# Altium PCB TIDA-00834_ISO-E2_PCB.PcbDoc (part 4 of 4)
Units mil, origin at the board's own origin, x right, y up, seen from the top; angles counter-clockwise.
Board outline 9055.12 x 4133.86 mil, 4 copper layers (Top Layer, GND, PWR, Bottom Layer), stack 61.92 mil thick; 647 components, 282 nets, 1430 pads, 409 vias.
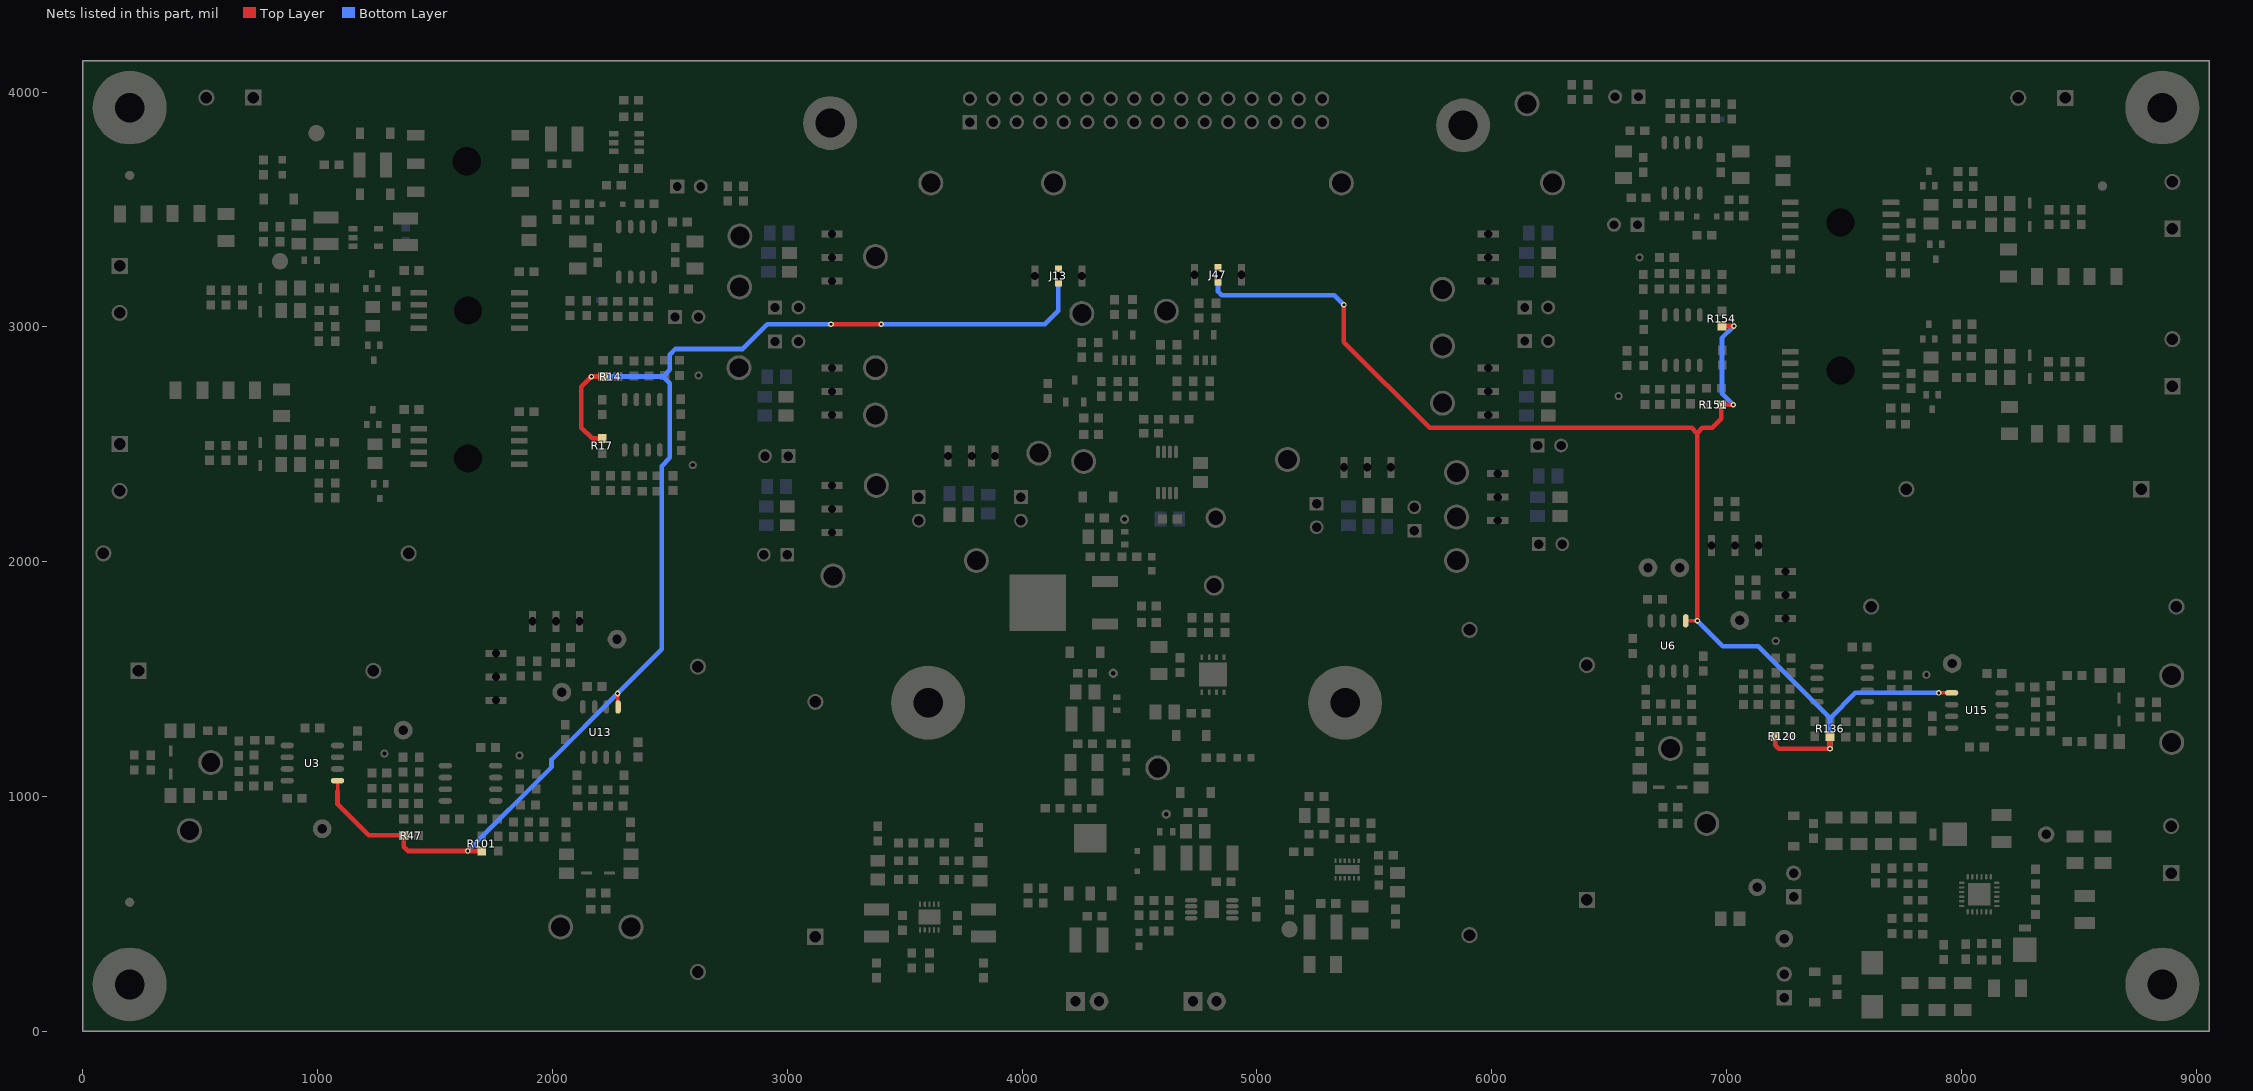
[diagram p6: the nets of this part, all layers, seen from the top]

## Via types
v1: diameter 24, hole 12, Top Layer to Bottom Layer, tented both sides, 388 vias
v2: diameter 19.68, hole 7.87, Top Layer to Bottom Layer, tented top, 15 vias
v3: diameter 19.68, hole 7.87, Top Layer to Bottom Layer, 5 vias
v4: diameter 40, hole 20, Top Layer to Bottom Layer, 1 vias

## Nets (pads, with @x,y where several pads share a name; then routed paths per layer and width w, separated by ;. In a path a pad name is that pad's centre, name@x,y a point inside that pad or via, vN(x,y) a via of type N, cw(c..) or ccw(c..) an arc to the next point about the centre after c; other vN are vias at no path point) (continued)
VBIAS: J13.2 R14.1 R17.1 R47.1 R101.1 U3.5 U13.5 | length 5956.5
  Top Layer w10: R47.1@1365.59,835.27 R47.1@1366.59,834.27 ; U13.5@2277.35,1383.99 U13.5@2279.41,1381.92
  Top Layer w15: 1084.88,1023.19 U3.5@1084.88,1067.52 ; U13.5@2277.35,1383.99 v1(2277.35,1439.09)
  Top Layer w20: 1084.88,1023.19 1084.88,967.72 1217.33,835.27 R47.1@1365.59,835.27 ; R47.1@1366.59,834.27 1366.59,786 1384,768.6 v1(1639.41,768.6) R101.1@1699.41,768.6 ; R17.1@2212.38,2524.84 2169.03,2524.84 2122.38,2571.49 2122.38,2744.86 v1(2165.87,2788.35) R14.1@2215.89,2788.35 ; v1(3186,3011) v1(3400,3011)
  Bottom Layer w20: v1(1639.41,768.6) 1996,1125.19 1996,1157.74 v1(2277.35,1439.09) 2465,1626.74 2465,2407.57 2500,2442.57 2500,2759.77 2471.42,2788.35 ; v1(2165.87,2788.35) 2471.42,2788.35 ; v1(3186,3011) 2915,3011 2810,2906 2524,2906 2500,2882 2500,2816.92 2471.42,2788.35 ; v1(3400,3011) 4097,3011 4154,3068 J13.2@4154,3217
VBIASB: J47.2 R120.1 R136.1 R151.1 R154.1 U6.5 U15.5 | length 5729
  Top Layer w15: U6.5@6825.43,1748.54 v1@6874.8,1748.54 ; v1(7902.91,1441.65) U15.5@7957.83,1441.65
  Top Layer w20: v1(5370,3094) 5370,2935 5735,2570 6851,2570 6873,2548 6874.8,2548 ; v1@6874.8,1748.54 6874.8,2548 ; R154.1@6980,3003.5 v1(7030.8,3003.5) ; v1(7028.25,2668.7) R151.1@6977.45,2668.7 6977.45,2608.45 6939,2570 6896.8,2570 6874.8,2548 ; R120.1@7206.79,1256.2 7206.79,1218.19 7221.12,1203.86 v1(7440.12,1203.86) R136.1@7440.12,1257.36
  Bottom Layer w20: J47.2@4834,3222 4834,3151 4850,3135 5329,3135 v1(5370,3094) ; v1(6875.12,1748.86) 6983.98,1640 7133.98,1640 7440.12,1333.86 ; v1(7028.25,2668.7) 6979.96,2716.99 6979.96,2952.66 v1(7030.8,3003.5) ; v1(7440.12,1203.86) 7440.12,1333.86 ; v1(7902.91,1441.65) 7547.91,1441.65 7440.12,1333.86
pads on no net: D23.3 D24.3 D25.3 D26.3 D27.3 D28.3 D29.3 D30.3 D31.3 D32.3 D33.3 D34.3 D35.3 D36.3 D37.3 D38.3 FID1.1 FID2.1 FID3.1 FID4.1 FID5.1 FID6.1 H1.1 H2.1 H3.1 H4.1 H9.1 H11.1 H13.1 H14.0 H15.1 H16.0 J1.2 J2.2 J31.2 J34.2 J48.2 J49.2 T1.3 T1.4 T2.3 T2.4 T3.3 T3.4 T4.3 T4.4 U5.12 U5.20 U10.1 U10.3 U10.7 U10.8 U11.2 U11.3 U11.6 U12.7 U24.4 U24.5 U26.13@5356.73,689.84 U26.13@5410.59,689.84

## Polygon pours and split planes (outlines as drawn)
NetC155_1 on Top Layer "NETC155_1_L01_P113" (solid, remove dead copper, pour order 113): 5453.5,640 5453.5,651.5 5463,661 5481,661 5502,640 5513.5,640 5543.5,640 5563.5,620 5613.5,620 5623.5,620 5628.5,615 5628.5,512.5 5621,505 5552,505 5538,519 5538,550.5 5488.5,600 5470.5,618 5453.5,635
GND1 on Top Layer "GND1_L01_P133" (solid, remove dead copper, pour order 133): 5560,790 5560,730 5570,720 5570,680 5570,655 5575,650 5630,650 5660,650 5680,670 5680,790 5660,810 5580,810
NetC161_1 on Top Layer "NETC161_1_L01_P131" (solid, remove dead copper, pour order 131): 3715,817.09 3725,827.09 3875,827.09 3885,817.09 3885,722.09 3885,707.09 3875,697.09 3820,697.09 3775,697.09 3765,687.09 3765,632.09 3765,602.09 3745,582.09 3705,582.09 3690,567.09 3680,567.09 3670,577.09 3715,622.09
NetC161_2 on Top Layer "NETC161_2_L01_P129" (solid, remove dead copper, pour order 129): 3650,812.09 3655,817.09 3665,817.09 3685,817.09 3690,812.09 3690,732.09 3690,627.09 3650,587.09 3640,587.09 3632,595.09 3632,749.09 3650,767.09 3650,802.09 3650,812.09 3655,817.09
NetC159_2 on Top Layer "NETC159_2_L01_P127" (solid, remove dead copper, pour order 127): 3515,812.09 3515,817.09 3520,822.09 3550,822.09 3555,817.09 3555,787.09 3555,783.09 3575,763.09 3575,572.55 cw(c3569.59,581.74) 3570,571.09 3565,572.09 3515,622.09
NetC159_1 on Top Layer "NETC159_1_L01_P125" (solid, remove dead copper, pour order 125): 3325,822.09 3330,827.09 3370,827.09 3405,827.09 3415,817.09 3415,792.09 3415,757.09 3425,747.09 3470,747.09 3480,747.09 3490,737.09 3490,712.09 3490,617.09 3535,572.09 3535,567.09 3525,557.09 3500,557.09 3440,617.09 3440,692.09 3430,702.09 3400,702.09 3330,702.09 3325,707.09
NetC164_2 on Top Layer "NETC164_2_L01_P123" (solid, remove dead copper, pour order 123): 3670,437.09 3680,447.09 3725,447.09 3760,447.09 3780,427.09 3895,427.09 3900,427.09 3910,417.09 3910,285 3900,275 3760,275 3750,285 3750,337.09 3670,417.09
GND1 on Top Layer "GND1_L01_P121" (solid, remove dead copper, pour order 121): 3325,662.09 3335,672.09 3380,672.09 3405,672.09 3415,662.09 3415,613.09 3415,607.09 3455,567.09 3510,512.09 3590,512.09 3670,512.09 3715,557.09 3760,557.09 3780,577.09 3790,587.09 3790,647.09 3790,652.09 3800,662.09 3875,662.09 3900,662.09 3915,647.09 3920,642.09 3920,572.09 3920,517.09 3905,502.09 3900,497.09 3825,497.09 3765,497.09 3745,477.09 3710,477.09 3680,477.09 3658.62,455.7 3628.77,455.7 3560.3,455.7 3543.91,472.09 3490,472.09 3455,472.09 3430,497.09 3340,497.09 3335,497.09 3325,507.09
GND1 on Top Layer "GND1_L01_P115" (solid, remove dead copper, pour order 115): 5198.5,780 5198.5,790 5198.5,795 5203.5,800 5238.5,800 5240.69,800 5243.5,797.18 5243.5,720 5253.5,710 5258.5,705 5348.5,705 5428.5,705 5433.5,700 5433.5,685 5433.5,680 5428.5,675 5258.5,675 5248.5,665 5248.5,645 5248.5,625 5273.5,600 5288.5,585 5288.5,525 5248.5,485 5248.5,388.5 5240,380 5208.28,380 5198.5,389.77 5198.5,795
NetC153_1 on Top Layer "NETC153_1_L01_P111" (solid, remove dead copper, pour order 111): 5265,1025 5265,788.5 5298.51,755 5338.5,755 5345,761.5 5345,775 5340,780 5323.51,780 5303.5,800 5303.5,835 5303.5,1026.5 5295,1035 5275,1035
NetC151_2 on Top Layer "NETC151_2_L01_P109" (solid, remove dead copper, pour order 109): 5369.5,660 5369.5,621 5369.5,607 5349.5,587 5336.5,587 5327.5,587 5315.5,575 5315.5,399 5321.5,393 5344.5,393 5356.5,393 5363.5,400 5363.49,569.98 5378.5,585 5378.5,590 5378.5,660
+6V_VDC on Top Layer "+6V_VDC_L01_P072" (solid, remove dead copper, pour order 72): 1205,3850 1205,3535 1188.98,3518.98 1091.02,3518.98 1075,3535 1075,3610 1075,3725 1075,3810 1075,3850 1085,3860 1175,3860 1195,3860
AGND on Top Layer "Top Layer-No Net" (solid, remove dead copper, pour order 58): 4542.4,1545 4717.4,1545 4742.4,1570 4892.05,1570 4902.4,1559.65 4902.4,1480.35 4892.05,1470 4712.4,1470 4682.4,1440 4607.4,1440 4592.4,1425 4592.4,1305 4577.4,1290 4542.4,1290 4527.4,1305 4527.4,1530
+3.3V on Top Layer "Top Layer-No Net" (solid, remove dead copper, pour order 56): 4446.5,2301 4446.5,2245.15 4386.5,2185.15 4386.5,2076 4381.5,2071 4336.5,2071 4331.5,2076 4331.5,2231 4371.5,2271 4371.5,2301 4381.5,2311 4436.5,2311
AGND on Top Layer "Top Layer-No Net" (solid, remove dead copper, pour order 54): 4271.5,2301 4271.5,2236 4281.5,2226 4306.5,2226 4311.5,2221 4311.5,2008.5 4186.5,1883.5 4186.5,1721.5 4170,1705 3964,1705 3948,1721 3948,1928.56 3964.44,1945 4059,1945 4186.5,2072.5 4186.5,2301 4196.5,2311 4261.5,2311
+12V on Top Layer "Top Layer-No Net" (solid, remove dead copper, pour order 50): 4330,1640 4420,1640 4435,1625 4435,1500 4415,1480 4370,1480 4362.91,1472.91 4362.91,1460 4362.91,1420 4352.91,1410 4322.91,1410 4292.91,1410 4282.91,1420 4282.91,1550 4282.91,1555 4312.91,1585 4312.91,1622.91
NetC54_2 on Top Layer "Top Layer-No Net" (solid, remove dead copper, pour order 48): 4235,1175 4235,995 4250,980 4250,935 4245,930 4145,930 4140,935 4140,1175 4145,1180 4230,1180
NetC54_1 on Top Layer "Top Layer-No Net" (solid, remove dead copper, pour order 46): 4365,760 4220,760 4215,765 4215,880 4225,890 4265,890 4277.91,902.91 4277.91,1265 4297.91,1285 4297.91,1360 4297.91,1373.15 4307.91,1383.15 4334.84,1383.15 4364.76,1383.15 4372.91,1375 4372.91,1355 4372.91,1280 4392.91,1260 4397.91,1255 4397.91,1200 4372.91,1175 4372.91,767.91
AGND on Top Layer "Top Layer-No Net" (solid, remove dead copper, pour order 44): 4095,1640 4210,1640 4222.91,1627.09 4222.91,1565 4227.91,1560 4251.46,1560 4257.91,1553.54 4257.91,1403.15 4237.91,1383.15 4237.91,1270 4257.91,1250 4257.91,1215 4247.91,1205 4095,1205 4085,1215 4085,1630
AGND on Top Layer "Top Layer-No Net" (solid, remove dead copper, pour order 42): 4015,565 4115,565 4125,555 4125,520 4130,515 4162.92,515 4257.91,515 4287.91,515 4292.91,510 4292.91,485 4292.91,465 4282.91,455 4252.91,425 4252.91,400 4252.91,335 4242.91,325 4187.91,325 4015,325 4005,335 4005,555
+14V on Top Layer "Top Layer-No Net" (solid, remove dead copper, pour order 40): 4317.91,512.91 4325,520 4415,520 4420,515 4420,305 4410,295 4330,295 4317.91,307.09
-14V on Top Layer "Top Layer-No Net" (solid, remove dead copper, pour order 38): 4867.4,795 4877.4,805 4962.4,805 4972.4,795 4972.4,620 4957.4,605 4882.4,605 4867.4,620
-12V on Top Layer "Top Layer-No Net" (solid, remove dead copper, pour order 36): 4669.4,940.6 4625,985 4625,1065 4635,1075 4685,1075 4692.4,1067.6 4692.4,992.6 4722.4,962.6 4722.4,920 4722.4,830 4712.4,820 4678.4,820 4669.4,829
AGND on Top Layer "Top Layer-No Net" (solid, remove dead copper, pour order 34): 4604.69,441.64 4609.69,446.64 4769.65,446.64 4777.4,454.4 4777.4,590 4765.76,601.64 4684.69,601.64 4674.69,611.64 4674.69,780.9 4685.42,791.64 4744.69,791.64 4749.69,796.64 4749.69,961.64 4784.69,996.64 4784.69,1091.64 4794.69,1101.64 4855.76,1101.64 4867.4,1090 4867.4,855 4809.69,797.28 4809.69,686.64 4837.4,658.92 4837.4,394.36 4824.69,381.64 4615.76,381.64 4604.68,392.72
NetC35_1 on Top Layer "Top Layer-No Net" (solid, remove dead copper, pour order 20): 7210.12,798.86 7220.12,808.86 7325.12,808.86 7335.12,818.86 7335.12,833.86 7345.12,843.86 7405.12,843.86 7425.12,823.86 7815.12,823.86 7835.12,843.86 7835.12,973.86 7840.12,978.86 7890.12,978.86 7895.12,973.86 7895.12,763.86 7945.12,713.86 7945.12,623.86 7945.12,603.86 7935.12,593.86 7900.12,593.86 7880.12,613.86 7880.12,723.86 7850.12,753.86 7665.12,753.86 7655.12,743.86 7655.12,688.86 7645.12,678.86 7570.12,678.86 7560.12,688.86 7560.12,743.86 7550.12,753.86 7370.12,753.86 7350.12,733.86 7350.12,648.86 7340.12,638.86 7220.12,638.86 7210.12,648.86
GND1 on Top Layer "Top Layer-No Net" (solid, remove dead copper, pour order 28): 8380.12,893.86 8125.12,893.86 8105.12,913.86 8105.12,963.86 8120.12,978.86 8955.12,978.86 8985.12,948.86 8985.12,828.86 8965.12,808.86 8465.12,808.86 8460.12,808.86 8445.12,823.86 8445.12,873.86 8425.12,893.86
+5V_IN on Top Layer "Top Layer-No Net" (solid, remove dead copper, pour order 6): 8140.12,608.86 8140.12,683.86 8175.12,718.86 8360.12,718.86 8385.12,743.86 8970.12,743.86 8985.12,728.86 8985.12,568.86 8965.12,548.86 8380.12,548.86 8365.12,563.86 8365.12,663.86 8355.12,673.86 8200.12,673.86 8190.12,663.86 8190.12,608.86
NetD4_1 on Top Layer "Top Layer-No Net" (solid, remove dead copper, pour order 24): 8215.12,398.86 8200.12,383.86 8200.12,263.86 8225.12,238.86 8225.12,113.86 8235.12,103.86 8330.12,103.86 8340.12,113.86 8340.12,388.86 8330.12,398.86
NetD7_1 on Top Layer "Top Layer-No Net" (solid, remove dead copper, pour order 18): 7920.12,973.86 7920.12,773.86 7965.12,728.86 7965.12,623.86 7980.12,608.86 8010.12,608.86 8015.12,613.86 8015.12,643.86 8005.12,653.86 8005.12,723.86 8050.12,768.86 8250.12,768.86 8270.12,788.86 8270.12,813.86 8250.12,833.86 8070.12,833.86 8055.12,848.86 8055.12,973.86 8050.12,978.86 7925.12,978.86
GND1 on Top Layer "Top Layer-No Net" (solid, remove dead copper, pour order 16): 7210.12,923.86 7210.12,907.86 7219.12,898.86 7312.12,898.86 7315.12,898.86 7345.12,868.86 7389.12,868.86 7400.12,868.86 7415.12,883.86 7418.12,886.86 7692.12,886.86 7803.12,886.86 7810.12,893.86 7810.12,973.86 7805.12,978.86 7223.12,978.86 7210.12,965.86 7210.12,924.86
NetD4_2 on Top Layer "Top Layer-No Net" (solid, remove dead copper, pour order 26): 8115.12,509.86 8115.12,448.86 8130.12,433.86 8200.12,433.86 8205.12,433.86 8210.12,428.86 8215.12,423.86 8245.12,423.86 8345.12,423.86 8370.12,398.86 8370.12,343.86 8380.12,333.86 8610.12,333.86 8620.12,343.86 8620.12,463.86 8620.12,473.86 8610.12,483.86 8605.12,488.86 8485.12,488.86 8395.12,488.86 8365.12,458.86 8260.12,458.86 8255.12,458.86 8230.12,483.86 8230.12,518.86 8230.12,523.86 8220.12,533.86 8215.12,538.86 8165.12,538.86 8144.12,538.86
NetC25_1 on Top Layer "Top Layer-No Net" (solid, remove dead copper, pour order 32): 7160.12,293.86 7160.12,238.86 7190.12,208.86 7255.12,208.86 7290.12,208.86 7320.12,238.86 7380.12,238.86 7420.12,238.86 7430.12,228.86 7430.12,223.86 7430.12,208.86 7435.12,203.86 7440.12,198.86 7465.12,198.86 7500.12,198.86 7510.12,208.86 7510.12,233.86 7520.12,243.86 7675.12,243.86 7695.12,243.86 7710.12,228.86 7710.12,213.86 7710.12,188.86 7720.12,178.86 7770.12,178.86 8070.12,178.86 8080.12,168.86 8080.12,143.86 8087.76,136.22 8157.48,136.22 8165.12,143.86 8165.12,238.86 8155.12,248.86 8115.12,248.86 8105.12,258.86 8105.12,318.86 8100.12,323.86 8005.12,323.86 8000.12,318.86 8000.12,258.86 7990.12,248.86 7800.12,248.86 7785.12,263.86 7785.12,303.86 7785.12,333.86 7770.12,348.86 7768.98,350 7691.97,350 7191.26,350 7160.12,318.86
GND1 on Top Layer "GND1_L01_P068" (solid, remove dead copper, pour order 68): 7325.12,133.86 7335.12,143.86 7400.12,143.86 7420.12,143.86 7430.12,153.86 7430.12,163.86 7440.12,173.86 7510.12,173.86 7550.12,173.86 7570.12,153.86 7640.12,153.86 7690.12,153.86 7705.12,138.86 7730.12,113.86 7755.12,113.86 8155.12,113.86 8165.12,103.86 8165.12,73.86 8165.12,53.86 8140.12,28.86 8005.12,28.86 7350.12,28.86 7325.12,53.86
+5.0V_VDC on Top Layer "+5.0V_VDC_L01_P077" (solid, remove dead copper, pour order 77): 700,3670 750,3670 790,3670 795,3665 795,3630 795,3410 790,3405 725,3405 700,3405 690,3415 690,3660
NetC49_1 on Top Layer "NETC49_1_L01_P135" (solid, remove dead copper, pour order 135): 4425,2084 4441,2084 4456.16,2084 4460,2080.16 4460,2050 4445,2035 4445,2021 4445,1905 4430,1890 4405,1890 4300,1890 4295,1895 4295,1904 4295,1950 4334,1989 4335,1990 4335,2008 4335,2036 4339,2040 4361,2040 4381,2040
NetC157_2 on Top Layer "NETC157_2_L01_P137" (solid, remove dead copper, pour order 137): 3530,450 3465,450 3455,450 3435,430 3330,430 3305,430 3295,420 3295,390 3295,310 3295,295 3295,285 3305,275 3370,275 3435,275 3445,285 3450,290 3450,360 3450,365 3460,375 3480,395 3510,395 3520,395 3538.07,413.07 3538.07,441.81
GND1 on GND "GND1_L02_P060" (solid, remove dead copper, pour order 60): 8975,1000 7100,1000 7025,925 7025,300 6975,250 5760,250 5725,285 5725,980 5705,1000 5010,1000 5000,990 5000,280 4970,250 4505,250 4455,300 3880,300 3850,330 3850,860 3835,875 3335,875 3325,865 3325,250 3325,50 3345,30 5015,30 8605,30 8625,50 8625,410 8639.99,424.99 8974.99,424.99 9000,450 9000,975
GND2 on GND "GND2_L02_P064" (solid, remove dead copper, pour order 64): 7290,4035 6250,4035 6238.39,4023.39 6238.39,3918.34 6388.39,3768.34 6388.39,3578.34 6390.35,3464.65 6480,3375 7075,3375 7125,3425 7125,3610 7195,3680 7285,3680 7300,3695 7300,3775 7300,4025
GND_VDC on GND "GND_VDC_L02_P075" (solid, remove dead copper, pour order 75): 50,3700 75,3725 200,3725 400,3725 425,3750 425,4075 450,4100 1350,4100 1450,4100 1475,4075 1475,4000 1475,2275 1475,2250 1450,2225 1275,2225 75,2225 50,2250 50,3700
GND_VDC on GND "GND_VDC_L02_P081" (solid, remove dead copper, pour order 81): 7650,4050 7650,4075 7675,4100 7800,4100 8600,4100 8625,4075 8625,3750 8650,3725 8675,3725 9000,3725 9025,3700 9025,2520 9000,2495 7680,2495 7650,2525
GND on GND "GND_L02_P087" (solid, remove dead copper, pour order 87): 1825,4000 1850,4025 2175,4025 2800,4025 2825,4025 2850,4000 2850,3850 2850,3025 2800,2975 2250,2975 2075,2975 2000,3050 2000,3275 2000,3400 1975,3425 1925,3425 1850,3425 1825,3450
AGND on GND "AGND_L02_P073" (solid, remove dead copper, pour order 73): 50,1450 50,1925 50,1950 75,1975 1800,1975 1825,2000 1825,3375 1845,3395 1955,3395 1975,3375 1975,2954 2004,2925 2790,2925 2875,3010 2875,3850 2875,4006 2894,4025 6075,4025 6350,3750 6350,3460 6460,3350 6550,3350 7100,3350 7150,3400 7150,3600 7200,3650 7285,3650 7300,3635 7300,2250 7325,2225 8975,2225 9025,2175 9025,1050 9000,1025 7075,1025 7000,950 7000,750 7000,325 6950,275 5770,275 5750,295 5750,995 5720,1025 5000,1025 4975,1000 4975,295 4955,275 4520,275 4445,350 4185,350 4160,325 3890,325 3875,340 3875,895 3860,910 3320,910 3300,890 3300,275 3300,50 450,50 425,75 425,150 425,400 400,425 250,425 75,425 50,450 49.41,450.59
+5.0V_VDC on PWR "+5.0V_VDC_L03_P079" (solid, remove dead copper, pour order 79): 100,3650 125,3675 230,3675 450,3675 475,3700 475,3890 475,4000 500,4025 570,4025 865,4025 1400,4025 1425,4000 1425,3325 1450,3300 1450,3275 1425,3250 1425,2725 1450,2700 1450.75,2699.25 1450.75,2674.25 1450.75,2665.75 1425,2640 1425,2590 1425,2300 1400,2275 1275,2275 125,2275 100,2300
+5.0V_VDC on PWR "+5.0V_VDC_L03_P085" (solid, remove dead copper, pour order 85): 7700,4025 7725,4050 7800,4050 8550,4050 8575,4025 8575,3725 8575,3700 8600,3675 8675,3675 8925,3675 8950,3650 8950,3550 8950,2550 8925,2525 7750,2525 7725,2525 7700,2525 7675,2550 7675,2575 7700,2600 7700,3150 7675,3175 7675,3200 7700,3225 7700,3275
+12V on PWR "+12V_L03_P099" (solid, remove dead copper, pour order 99): 100,1900 125,1925 1825,1925 1875,1975 1875,3950 1900,3975 7225,3975 7250,3950 7250,2225 7300,2175 8925,2175 8950,2150 8950,1100 8925,1075 7025,1075 6950,1000 6950,350 6925,325 4025,325 4000,300 4000,125 3975,100 500,100 475,125 475,425 425,475 125,475 100,500
-12V on Bottom Layer "-12V_L04_P097" (solid, remove dead copper, pour order 97): 800,75 825,50 3525,50 3910,50 4050,190 4050,645 4080,675 4150,675 4835,675 4955,675 4980,650 4980,300 5100,180 6760,180 7175,595 7175,975 7250,1050 7430,1050 7750,1370 8125,1370 8210,1455 8210,1565 8195,1580 8160,1580 8150,1570 8150,1480 8085,1415 7690,1415 7575,1300 7450,1175 7425,1175 7410,1190 7410,1315 7120,1605 6995,1605 6975,1585 6945,1555 6885,1555 6880,1550 6880,1520 6885,1515 6985,1515 7015,1545 7055,1545 7075,1525 7270,1330 7270,1195 7250,1175 7125,1175 7015,1065 7015,725 6630,340 5195,340 5125,410 5125,1170 5085,1210 3930,1210 3890,1170 3890,305 3785,200 3465,200 1015,200 975,240 975,555 1020,600 2114,600 2450,936 2450,1150 2450,1175 2435,1190 2350,1190 2345,1185 2345,1145 2390,1100 2390,1045 2365,1020 2180,1020 2085,925 1850,690 1605,690 1575,720 1575,895 1655,975 1655,1633.22 1836.78,1815 2265,1815 2425,1975 2425,2450 2425,2575 2275,2725 2150,2725 2125,2700 2122.38,2697.38 2122.38,2625 2122.38,2614.84 2212.38,2524.84 2379.5,2357.72 2379.5,2327.2 2379.5,2004.5 2275,1900 1900,1900 1825,1900 1570,1645 1570,975 1395,800 915,800 890,825 890,1005 885,1010 840,1010 800,970

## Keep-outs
Keep-Out Layer:
  lines w10: 25,400 400,400 400,0 ; 25,3743.7 400,3743.7 400,4108.86 ; 8650,25 8650,400 9025,400 ; 8655.12,4108.86 8655.12,3743.7 9030.12,3743.7 ; 25,25 9030.12,25 9030.12,4108.86 25,4108.86 25,25
  text ".Layer_Name" at 577,-858.49 h60

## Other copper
Top Layer:
  region net +5V_IN: 8040.12,703.86 8040.12,648.86 8045.12,643.86 8105.12,643.86 8110.12,648.86 8110.12,703.86 8105.12,708.86 8045.12,708.86
  text ".Layer_Name" at 577,-858.49 h60
GND:
  pour cut-out: 5730,3990 5730,3715 6030,3715 6030,3990
  pour cut-out: 3032.4,4005.35 3032.4,3730.35 3332.4,3730.35 3332.4,4005.35
  pour cut-out: 3400,1600 3400,1200 3800,1200 3800,1600
  pour cut-out: 5175,1600 5175,1200 5575,1200 5575,1600
  text ".Layer_Name" at 577,-858.49 h60
PWR:
  pour cut-out: 4050,325 4050,485 4085,485 4085,325
  pour cut-out: 5730,3990 5730,3715 6030,3715 6030,3990
  pour cut-out: 3032.4,4005.35 3032.4,3730.35 3332.4,3730.35 3332.4,4005.35
  pour cut-out: 3400,1600 3400,1200 3800,1200 3800,1600
  pour cut-out: 5175,1600 5175,1200 5575,1200 5575,1600
  pour cut-out: 3715,3975 3715,3825 3725,3815 5315,3815 5330,3830 5330,3960 5345,3975 5345,3830 5325,3810 3720,3810 3710,3820 3710,3970
  text ".Layer_Name" at 577,-858.49 h60
Bottom Layer:
  text ".Layer_Name" at 577,-858.49 h60
Multi-Layer:
  pour cut-out: 1495.39,4011 1495.39,2200 0,2200 0,2080 1795,2080 1795,2099.61 1795.39,2100 1795.39,4011
  pour cut-out: 7633,4011 7633,2512 7670,2475 9055.12,2475 9055.12,2360 7380,2360 7333,2407 7333,4011

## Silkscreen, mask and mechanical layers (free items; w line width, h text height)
Top Overlay:
  drawing of 256 lines, arcs and shapes, not listed
  text "2" at 3760,4035 h60
  text "14" at 4335,4035 h60
  text "20" at 4635,4035 h60
  text "8" at 4055,4030 h60
  text "26" at 4930,4030 h60
  text "32" at 5225,4030 h60
  text "19" at 4627.4,3740 h60
  text "7" at 4070,3735 h60
  text "13" at 4345,3735 h60
  text "25" at 4935,3735 h60
  text "31" at 5230,3735 h60
  text "1" at 3765,3730 h60
  text "TIDA-00834_ISO-E2" at 1669,100 h108.27
  text ".Layer_Name" at 577,-858.49 h60
Bottom Overlay:
  text "2" at 3780,4035 h60
  text "14" at 4425,4035 h60
  text "20" at 4735,4035 h60
  text "8" at 4115,4030 h60
  text "26" at 5030,4030 h60
  text "32" at 5325,4030 h60
  text "19" at 4720,3745 h60
  text "7" at 4090,3735 h60
  text "13" at 4445,3735 h60
  text "25" at 5030,3735 h60
  text "31" at 5310,3735 h60
  text "1" at 3785,3730 h60
  text ".Layer_Name" at 577,-858.49 h60
Top Paste:
  text ".Layer_Name" at 577,-858.49 h60
Bottom Paste:
  text ".Layer_Name" at 577,-858.49 h60
Top Solder:
  text ".Layer_Name" at 577,-858.49 h60
  text ".Layer_Name" at 577,-858.49 h60
Bottom Solder:
  text ".Layer_Name" at 577,-858.49 h60
Drill Guide:
  text ".Layer_Name" at 577,-858.49 h60
M1 Board Outline:
  the board outline again, w10
  text ".Layer_Name" at 584,-851.99 h60
M2 Board Dimensions:
  rectangle: 125,-400 500,-275
  rectangle: 0,-275 125,-150
  lines w7: 0,-275 1000,-275 ; 125,-400 125,-150 ; 250,-400 250,-150 ; 500,-400 500,-150 ; 750,-400 750,-150 ; 0,-400 0,-150 1000,-150 1000,-400 0,-400
M3 3D STEP Top:
  text ".Layer_Name" at 577,-858.49 h60
M4 3D STEP Bottom:
  text ".Layer_Name" at 577,-858.49 h60
M5 Assembly Top:
  circle w6: c4762.4,1445 r7.07
  circle w6: c1132,3417 r5
  circle w6: c1205,3136 r5
  circle w6: c1266,2950 r5
  circle w6: c1209,2552 r5
  circle w6: c1289,2362 r5
  circle w6: c2242,3822 r5
  circle w6: c4397.6,2839 r5
  circle w6: c4742.6,2840 r5
  circle w6: c4230,631 r5
  circle w6: c7901,2740 r5
  circle w6: c7834,2921 r5
  circle w6: c7916,3379 r5
  circle w6: c7834,3573 r5
  circle w6: c4186.6,2658 r5
  lines w4: 4742.4,1425 4742.4,1615 4752.4,1615 4882.4,1615 4882.4,1425 4742.4,1425
  lines w6: 420,1120 425,1115 465,1115 470,1110 ; 420,1170 425,1175 465,1175 470,1180 ; 445,1095 445,1115 ; 445,1135 445,1155 ; 445,1195 445,1175 ; 2145,735 2165,735 ; 2160,760 2165,755 2165,715 2170,710 ; 2185,735 2205,735 ; 2220,710 2225,715 2225,755 2230,760 ; 2245,735 2225,735 ; 6710,1105 6730,1105 ; 6725,1130 6730,1125 6730,1085 6735,1080 ; 6750,1105 6770,1105 ; 6785,1080 6790,1085 6790,1125 6795,1130 ; 6810,1105 6790,1105 ; 8580,1335 8585,1340 8625,1340 8630,1345 ; 8580,1405 8585,1400 8625,1400 8630,1395 ; 8605,1320 8605,1340 ; 8605,1360 8605,1380 ; 8605,1420 8605,1400 ; 445,1115 425,1135 465,1135 445,1115 ; 445,1175 465,1155 425,1155 445,1175 ; 2165,735 2185,715 2185,755 2165,735 ; 2225,735 2205,755 2205,715 2225,735 ; 6730,1105 6750,1125 6750,1085 6730,1105 ; 6790,1105 6770,1085 6770,1125 6790,1105 ; 8605,1340 8585,1360 8625,1360 8605,1340 ; 8605,1400 8625,1380 8585,1380 8605,1400
  lines w10: -292,-930.17 6308,-930.17 ; -292,-726.83 6310,-726.83 ; -292,-523.5 -292,-1133.5 3713,-1133.5 6310,-1133.5 6310,-523.5 -291.5,-523.5 -291.5,-1133.5 1284,-1133.5 ; 2173,-1133.5 2173,-523.5 ; 3440,-726.83 3440,-523.5 ; 4280,-726.83 4280,-523.5 ; 4902,-1140 4902,-937.17
  text "COMPONENTS MARKED 'DNP' SHOULD NOT BE POPULATED." at 1153.5,-318.5 h60
  text "ASSEMBLY VARIANT:" at 1153,-434 h60
  text ".VariantName" at 2189,-434 h60
  text ".PRJ_Number" at 2725,-650 h50
  text "PCB VIEWED FROM TOP SIDE" at -228.5,-655.67 h60
  text "BOARD #:" at 2248,-655.67 h60
  text "REV:" at 3638,-655.67 h60
  text ".PCB_Rev" at 3929.5,-655.67 h60
  text "SVN REV:" at 4476,-655.67 h60
  text ".VersionControl_RevNumber" at 4982,-655.67 h60
  text ".Layer_Name" at 577,-858.49 h60
  text "TID #:" at 2248,-859 h60
  text ".TID" at 2793.5,-859 h60
  text "PLOT NAME =" at -228.5,-1064.34 h60
  text ".plot_File_Name" at 577,-1064.34 h60
  text "GENERATED    :" at 2250,-1064.34 h60
  text ".Print_Date" at 3119.5,-1064.34 h60
  text ".Print_Time" at 3848.5,-1064.34 h60
  text "TEXAS INSTRUMENTS" at 5113,-1064.34 h60
M6 Assembly Bottom:
  circle w6: c7885,3572 r4.12
  circle w6: c7863.88,3377 r4.12
  circle w6: c7884.88,2921 r4.12
  circle w6: c7848.88,2739 r4.12
  circle w6: c1254.88,3137 r4.12
  circle w6: c1214.88,2949 r4.12
  circle w6: c1259.88,2559 r4.12
  circle w6: c1238.88,2359 r4.12
  circle w20: c3683,3870 r14.87
  lines w10: -292.5,-727.33 6309.5,-727.33 ; -290.5,-930.67 6309.5,-930.67 ; 1115.5,-1140.5 1115.5,-937.67 ; 1737.5,-727.33 1737.5,-524 ; 2577.5,-727.33 2577.5,-524 ; 3844.5,-1134 3844.5,-524 ; 4733.5,-1134 6309,-1134 6309,-524 -292.5,-524 -292.5,-1134 2304.5,-1134 6309.5,-1134 6309.5,-524
  text "COMPONENTS MARKED 'DNP' SHOULD NOT BE POPULATED." at 6102,-318 h60
  text ".VariantName" at 5058,-434 h60
  text "ASSEMBLY VARIANT:" at 6097,-434 h60
  text ".PRJ_Number" at 3305,-655 h50
  text ".VersionControl_RevNumber" at 1035.5,-656.17 h60
  text "SVN REV:" at 1541.5,-656.17 h60
  text ".PCB_Rev" at 2088,-656.17 h60
  text "REV:" at 2379.5,-656.17 h60
  text "BOARD #:" at 3769.5,-656.17 h60
  text "PCB VIEWED FROM BOTTOM SIDE" at 6246,-656.17 h60
  text ".Layer_Name" at 5805,-840 h60
  text ".TID" at 3224,-859.5 h60
  text "TID #:" at 3769.5,-859.5 h60
  text "TEXAS INSTRUMENTS" at 904.5,-1064.84 h60
  text ".Print_Time" at 2169,-1064.84 h60
  text ".Print_Date" at 2898,-1064.84 h60
  text "GENERATED    :" at 3767.5,-1064.84 h60
  text ".plot_File_Name" at 5440.5,-1064.84 h60
  text "PLOT NAME =" at 6246,-1064.84 h60
M9 Title Sheet:
  drawing of 57 lines, arcs and shapes, not listed
  text "1" at 739.84,8036.5 h70
  text "2" at 3235.5,8036.5 h70
  text "3" at 5724.84,8036.5 h70
  text "4" at 8231.51,8036.5 h70
  text "5" at 10730.5,8036.5 h70
  text "6" at 13235.5,8036.5 h70
  text "A" at -416.5,6893.5 h70
  text "A" at 14383.5,6893.5 h70
  text "B" at -416.5,4513.5 h70
  text "B" at 14383.5,4513.5 h70
  text "C" at -416.5,2138.5 h70
  text "C" at 14383.5,2138.5 h70
  text "PROJECT TITLE:" at 11343.5,277.5 h45
  text ".PRJ_Title" at 11393.5,144.17 h70
  text "DESIGNED FOR:" at 11343.5,-23.5 h45
  text ".PRJ_Customer" at 11393.5,-163.5 h70
  text "D" at -416.5,-231.5 h70
  text "D" at 14383.5,-231.5 h70
  text "FILE NAME:" at 11343.5,-323.5 h45
  text ".PCB_File_Name_No_Path" at 11393.5,-443.5 h70
  text "Texas Instruments (TI) and/or its licensors do not warrant the accuracy or completeness of this specification" at 6374,-605.34 h45
  text "ENGINEER:" at 11343.5,-613.5 h45
  text "LAYOUT BY:" at 12848.5,-613.5 h45
  text "or any information contained therein. TI and/or its licensors do not warrant that this design will meet" at 6329.01,-718 h45
  text ".PRJ_Engineer" at 11393.5,-768.49 h70
  text ".PCB_Layout" at 12899,-768.49 h70
  text "the specifications, will be suitable for your application or fit for any particular purpose, or will operate in" at 6329.01,-830.67 h45
  text "ALTIUM DESIGNER VERSION:" at 12848.5,-923.5 h45
  text "an implementation. TI and/or its licensors do not warrant that the design is production worthy. You should" at 6329.01,-943.33 h45
  text "completely validate and test your design implementation to confirm the system functionality for your application." at 6374,-1056 h45
  text ".print_Scale" at 11393.5,-1056.83 h70
  text ".Application_BuildNumber" at 12899,-1056.83 h70
  text "1" at 739.84,-1263.5 h70
  text "2" at 3235.5,-1263.5 h70
  text "3" at 5724.84,-1263.5 h70
  text "4" at 8231.51,-1263.5 h70
  text "5" at 10730.5,-1263.5 h70
  text "6" at 13235.5,-1263.5 h70
M10 Fab Notes:
  drawing of 189 lines, arcs and shapes, not listed
  text "DESIGN INFORMATION" at 12378.02,6201 h60
  text "MIN. TRACK WIDTH:" at 11733.46,6021 h60
  text "8" at 12829.7,6021 h60
  text "MIL" at 13068,6020 h60
  text "MIL" at 13070,5891 h60
  text "MIN. CLEARANCE:" at 11733.46,5889 h60
  text "7.874" at 12769.7,5889 h60
  text "MIN. VIA PAD SIZE:" at 11733.46,5757 h60
  text "19.685" at 12675,5745 h60
  text "MIL" at 13073,5745 h60
  text "0.15mm (5.906MIL)" at 12428.46,5615.29 h60
  text "EXTERNAL" at 13242,5613 h60
  text "MINIMUM ANNULAR RING" at 11404.23,5611 h60
  text "PER" at 11604.23,5493 h60
  text "IPC-D-275 CLASS 2 LEVEL C" at 11824.23,5493 h60
  text "MIL, HOLES" at 13312.46,5380.71 h60
  text "+/-" at 12920,5380 h60
  text "+/-" at 13774,5380 h60
  text "REGISTRATION TOLERANCES:" at 11404.23,5375 h60
  text "METAL" at 12604,5375 h60
  text "5" at 13180.2,5375 h60
  text "3" at 14013.2,5375 h60
  text "MIL" at 14129.46,5375 h60
  text "+/-" at 13774,5262 h60
  text "HOLE SIZE TOLERANCE (UNLESS OTHERWISE SPECIFIED):" at 11404.23,5257 h60
  text "3" at 14013.2,5257 h60
  text "MIL" at 14129.46,5257 h60
  text "MATERIAL:" at 11329.46,5047.54 h60
  text "FR-4 High Tg" at 12315.9,4907.21 h60
  text "FR-408" at 11750.46,4898.64 h60
  text "OTHER" at 13238.46,4898.64 h60
  text "X" at 12161,4895 h60
  text "62 MIL (1.6mm) +/-10%" at 12070.56,4735.92 h60
  text "THICKNESS:" at 11404.23,4731.64 h60
  text "X" at 11942.4,4731.64 h60
  text "OTHER" at 13355.46,4731.64 h60
  text "TOLERANCE:" at 11404.23,4573.64 h60
  text "X" at 12243.53,4573.64 h60
  text "ANSI IPC-6012 TYPE 3 CLASS 2" at 12430.48,4573.64 h60
  text "OTHER +/-" at 12430.46,4417.64 h60
  text "BOW & TWIST:" at 11404.23,4260.64 h60
  text "X" at 12243.53,4260.64 h60
  text "ANSI IPC-6012 TYPE 3 CLASS 2" at 12430.48,4260.64 h60
  text "OTHER +/-" at 12430.46,4102.13 h60
  text "DRILLING:" at 11329.46,3963.64 h60
  text "REFERENCE:" at 11404.23,3846.64 h60
  text "X" at 12052.46,3846.64 h60
  text "AS SHOWN" at 12239.46,3846.64 h60
  text "X" at 12953.46,3846.64 h60
  text "NC_DRILL FILES" at 13090.46,3846.64 h60
  text "PTH COPPER THICKNESS:" at 11404.23,3688.64 h60
  text "X" at 12534.46,3688.64 h60
  text "20-30 um" at 12671.46,3688.64 h60
  text "OTHER" at 13388.46,3688.64 h60
  text "BOARD FINISH:" at 11329.46,3529.64 h60
  text "SILKSCREEN:" at 11484.68,3411.64 h60
  text "X" at 12433.46,3411.64 h60
  text "TOP" at 12559.46,3411.64 h60
  text "X" at 12943.46,3411.64 h60
  text "BOTTOM" at 13070.46,3411.64 h60
  text "SILKSCREEN COLOR:" at 11484.68,3244.64 h60
  text "X" at 12432.42,3244.64 h60
  text "WHITE" at 12559.46,3244.64 h60
  text "OTHER" at 13070.46,3244.64 h60
  text "X" at 12563.42,3085.44 h60
  text "GREEN" at 12690.46,3085.44 h60
  text "OTHER" at 13308.46,3085.44 h60
  text "SOLDER RESIST COLOR:" at 11484.68,3074.64 h60
  text "X" at 12563.42,2915.44 h60
  text "MATTE" at 12690.46,2915.44 h60
  text "SEMI-GLOSS" at 13308,2914.8 h60
  text "IMMERSION GOLD (ENIG)" at 12390.46,2726.92 h60
  text "ENEPIG" at 13728,2723.64 h60
  text "SURFACE FINISH:" at 11329.46,2722.64 h60
  text "X" at 12203.51,2722.64 h60
  text "IMM. TIN/SILVER OR EQUIV" at 11659,2565.64 h60
  text "OTHER" at 13090.46,2565.64 h60
  text "ARRAY/PANEL:" at 11329.46,2386.64 h60
  text "CUT AND TRIM PER M1 BOARD OUTLINE" at 12390.46,2382.35 h60
  text "N.C. ROUTE" at 12390.46,2230.64 h60
  text "X" at 13069.46,2230.64 h60
  text "V. SCORE" at 13256.46,2230.64 h60
  text "CERTIFICATION:" at 11329.46,2093.64 h60
  text "MATERIALS AND WORKMANSHIP FOR ALL PCBS" at 12054.46,2093.64 h60
  text "TO MEET OR EXCEED THE REQUIREMENTS OF:" at 12054.46,1995.64 h60
  text "X" at 11680.96,1859.13 h60
  text "ANSI IPC-A-600F CLASS ->" at 11819.96,1859.13 h60
  text "X" at 13459.02,1859.13 h60
  text "2" at 13577.96,1859.14 h60
  text "1" at 13262.96,1857.64 h60
  text "3" at 13931.96,1857.64 h60
  text "X" at 12495.02,1699.64 h60
  text "RoHS" at 12631.96,1699.64 h60
  text "OTHER" at 13276.36,1699.64 h60
  text "PER ORDER" at 13673.42,1699.64 h60
  text "ALL BOARDS MUST MEET OR EXCEED UL94-V0 REQUIREMENTS." at 11357,1534 h60
  text "PCB MUST BEAR THE UL94V-0 UL REGISTERED MATERIAL ID NUMBER" at 11357,1414 h60
  text "VIA TENTING:" at 12546,1274 h60
  text "X" at 13306,1272 h60
  text "YES" at 13095.67,1264.92 h60
  text "NO" at 13460.47,1259.69 h60
  text "ADDITIONAL REQUIREMENTS:" at 11329.46,1240.64 h60
  text "IMPEDANCE CONTROL:" at 12568,1145 h60
  text "YES" at 13552,1144 h60
  text "X" at 14094,1137 h60
  text "NO" at 13927.47,1126.69 h60
  text "MICROSECTION:" at 11404.23,1125.64 h60
  text "YES" at 12309.96,1125.64 h60
  text "REQUIRED" at 13171.46,969.49 h60
  text "BARE BOARD ELEC. TEST:" at 11404.23,966.64 h60
  text "NONE" at 12709.96,966.64 h60
  text "X" at 13044.46,966.64 h60
  text "PER ORDER" at 13763.46,966.64 h60
M11 Gerber Information:
  lines w10: -292,-930.17 6308,-930.17 ; -292,-726.83 6310,-726.83 ; -292,-523.5 -292,-1133.5 3713,-1133.5 6310,-1133.5 6310,-523.5 -291.5,-523.5 -291.5,-1133.5 1284,-1133.5 ; 2173,-1133.5 2173,-523.5 ; 3440,-726.83 3440,-523.5 ; 4280,-726.83 4280,-523.5 ; 4902,-1140 4902,-937.17
  text ".PRJ_Number" at 2725,-650 h50
  text "ALL ARTWORK VIEWED FROM TOP SIDE" at -228.5,-655.67 h60
  text "BOARD #:" at 2248,-655.67 h60
  text "REV:" at 3638,-655.67 h60
  text ".PCB_Rev" at 3929.5,-655.67 h60
  text "SVN REV:" at 4476,-655.67 h60
  text ".VersionControl_RevNumber" at 4982,-655.67 h60
  text "LAYER NAME =" at -228.5,-858.49 h60
  text "TID #:" at 2248,-859 h60
  text ".TID" at 2793.5,-859 h60
  text "PLOT NAME =" at -228.5,-1064.34 h60
  text ".plot_File_Name" at 577,-1064.34 h60
  text "GENERATED    :" at 2250,-1064.34 h60
  text ".Print_Date" at 3119.5,-1064.34 h60
  text ".Print_Time" at 3848.5,-1064.34 h60
  text "TEXAS INSTRUMENTS" at 5113,-1064.34 h60
M12 Stackup:
  drawing of 295 lines, arcs and shapes, not listed
  text "Layer" at 9828.2,7871 h60
  text "Name" at 10238.11,7871 h60
  text "Material" at 11167.85,7871 h60
  text "Thickness" at 12027.62,7871 h60
  text "Constant" at 12677.46,7871 h60
  text "Board Layer Stack" at 13247.32,7871 h60
  text "1" at 9828.2,7751 h60
  text "Top Overlay" at 10238.11,7751 h60
  text "2" at 9828.2,7631 h60
  text "Top Solder" at 10238.11,7631 h60
  text "Solder Resist" at 11167.85,7631 h60
  text "0.40mil" at 12027.62,7631 h60
  text "4.3" at 12677.46,7631 h60
  text "3" at 9828.2,7511 h60
  text "Top Layer" at 10238.11,7511 h60
  text "Copper" at 11167.85,7511 h60
  text "1.38mil" at 12027.62,7511 h60
  text "4" at 9828.2,7391 h60
  text "Dielectric1" at 10238.11,7391 h60
  text "FR-4 High Tg" at 11167.85,7391 h60
  text "6.70mil" at 12027.62,7391 h60
  text "4.3" at 12677.46,7391 h60
  text "5" at 9828.2,7271 h60
  text "GND" at 10238.11,7271 h60
  text "Copper" at 11167.85,7271 h60
  text "1.38mil" at 12027.62,7271 h60
  text "6" at 9828.2,7151 h60
  text "Dielectric 2" at 10238.11,7151 h60
  text "FR-4 High Tg" at 11167.85,7151 h60
  text "43.00mil" at 12027.62,7151 h60
  text "4.3" at 12677.46,7151 h60
  text "7" at 9828.2,7031 h60
  text "PWR" at 10238.11,7031 h60
  text "Copper" at 11167.85,7031 h60
  text "1.38mil" at 12027.62,7031 h60
  text "8" at 9828.2,6911 h60
  text "Dielectric 3" at 10238.11,6911 h60
  text "FR-4 High Tg" at 11167.85,6911 h60
  text "6.70mil" at 12027.62,6911 h60
  text "4.3" at 12677.46,6911 h60
  text "9" at 9828.2,6791 h60
  text "Bottom Layer" at 10238.11,6791 h60
  text "Copper" at 11167.85,6791 h60
  text "1.38mil" at 12027.62,6791 h60
  text "10" at 9828.2,6671 h60
  text "Bottom Solder" at 10238.11,6671 h60
  text "Solder Resist" at 11167.85,6671 h60
  text "0.40mil" at 12027.62,6671 h60
  text "4.3" at 12677.46,6671 h60
  text "11" at 9828.2,6551 h60
  text "Bottom Overlay" at 10238.11,6551 h60
M13 Component Bodies Top:
  text ".Layer_Name" at 577,-858.49 h60
M14 Component Bodies Bottom:
  text ".Layer_Name" at 577,-858.49 h60
M15 Courtyards Top:
  text ".Layer_Name" at 577,-858.49 h60
M16 Courtyards Bottom:
  text ".Layer_Name" at 577,-858.49 h60
Drill Drawing:
  drawing of 185 lines, arcs and shapes, not listed
  text "Symbol" at 4590.51,7772.85 h72
  text "Quantity" at 4891.17,7772.85 h72
  text "Finished Hole Size" at 5223.33,7772.85 h72
  text "Plated" at 5859.81,7772.85 h72
  text "Hole Type" at 6119.01,7772.85 h72
  text "Drill Layer Pair" at 6494.25,7772.85 h72
  text "Hole Length" at 7218.8,7772.85 h72
  text "Routed Path Length" at 7840.35,7772.85 h72
  text "20" at 4891.17,7648.35 h60
  text "7.87mil (0.200mm)" at 5223.33,7648.35 h60
  text "PTH" at 5859.81,7648.35 h60
  text "Round" at 6119.01,7648.35 h60
  text "Top Layer - Bottom Layer" at 6494.25,7648.35 h60
  text "-" at 7218.8,7648.35 h60
  text "-" at 7840.35,7648.35 h60
  text "388" at 4891.17,7523.85 h60
  text "12.00mil (0.305mm)" at 5223.33,7523.85 h60
  text "PTH" at 5859.81,7523.85 h60
  text "Round" at 6119.01,7523.85 h60
  text "Top Layer - Bottom Layer" at 6494.25,7523.85 h60
  text "-" at 7218.8,7523.85 h60
  text "-" at 7840.35,7523.85 h60
  text "8" at 4891.17,7399.35 h60
  text "17.72mil (0.450mm)" at 5223.33,7399.35 h60
  text "PTH" at 5859.81,7399.35 h60
  text "Round" at 6119.01,7399.35 h60
  text "Top Layer - Bottom Layer" at 6494.25,7399.35 h60
  text "-" at 7218.8,7399.35 h60
  text "-" at 7840.35,7399.35 h60
  text "4" at 4891.17,7274.85 h60
  text "20.00mil (0.508mm)" at 5223.33,7274.85 h60
  text "PTH" at 5859.81,7274.85 h60
  text "Round" at 6119.01,7274.85 h60
  text "Top Layer - Bottom Layer" at 6494.25,7274.85 h60
  text "-" at 7218.8,7274.85 h60
  text "-" at 7840.35,7274.85 h60
  text "42" at 4891.17,7150.35 h60
  text "35.04mil (0.890mm)" at 5223.33,7150.35 h60
  text "PTH" at 5859.81,7150.35 h60
  text "Round" at 6119.01,7150.35 h60
  text "Top Layer - Bottom Layer" at 6494.25,7150.35 h60
  text "-" at 7218.8,7150.35 h60
  text "-" at 7840.35,7150.35 h60
  text "16" at 4891.17,7025.85 h60
  text "38.00mil (0.965mm)" at 5223.33,7025.85 h60
  text "PTH" at 5859.81,7025.85 h60
  text "Round" at 6119.01,7025.85 h60
  text "Top Layer - Bottom Layer" at 6494.25,7025.85 h60
  text "-" at 7218.8,7025.85 h60
  text "-" at 7840.35,7025.85 h60
  text "15" at 4891.17,6901.35 h60
  text "40.00mil (1.016mm)" at 5223.33,6901.35 h60
  text "PTH" at 5859.81,6901.35 h60
  text "Round" at 6119.01,6901.35 h60
  text "Top Layer - Bottom Layer" at 6494.25,6901.35 h60
  text "-" at 7218.8,6901.35 h60
  text "-" at 7840.35,6901.35 h60
  text "16" at 4891.17,6776.85 h60
  text "40.16mil (1.020mm)" at 5223.33,6776.85 h60
  text "PTH" at 5859.81,6776.85 h60
  text "Round" at 6119.01,6776.85 h60
  text "Top Layer - Bottom Layer" at 6494.25,6776.85 h60
  text "-" at 7218.8,6776.85 h60
  text "-" at 7840.35,6776.85 h60
  text "B" at 4565.2,6766.86 h55.33
  text "32" at 4891.17,6652.35 h60
  text "40.94mil (1.040mm)" at 5223.33,6652.35 h60
  text "PTH" at 5859.81,6652.35 h60
  text "Round" at 6119.01,6652.35 h60
  text "Top Layer - Bottom Layer" at 6494.25,6652.35 h60
  text "-" at 7218.8,6652.35 h60
  text "-" at 7840.35,6652.35 h60
  text "4" at 4891.17,6527.85 h60
  text "44.00mil (1.118mm)" at 5223.33,6527.85 h60
  text "PTH" at 5859.81,6527.85 h60
  text "Round" at 6119.01,6527.85 h60
  text "Top Layer - Bottom Layer" at 6494.25,6527.85 h60
  text "-" at 7218.8,6527.85 h60
  text "-" at 7840.35,6527.85 h60
  text "14" at 4891.17,6403.35 h60
  text "49.21mil (1.250mm)" at 5223.33,6403.35 h60
  text "PTH" at 5859.81,6403.35 h60
  text "Round" at 6119.01,6403.35 h60
  text "Top Layer - Bottom Layer" at 6494.25,6403.35 h60
  text "-" at 7218.8,6403.35 h60
  text "-" at 7840.35,6403.35 h60
  text "16" at 4891.17,6278.85 h60
  text "49.37mil (1.254mm)" at 5223.33,6278.85 h60
  text "PTH" at 5859.81,6278.85 h60
  text "Round" at 6119.01,6278.85 h60
  text "Top Layer - Bottom Layer" at 6494.25,6278.85 h60
  text "-" at 7218.8,6278.85 h60
  text "-" at 7840.35,6278.85 h60
  text "2" at 4891.17,6154.35 h60
  text "63.00mil (1.600mm)" at 5223.33,6154.35 h60
  text "PTH" at 5859.81,6154.35 h60
  text "Round" at 6119.01,6154.35 h60
  text "Top Layer - Bottom Layer" at 6494.25,6154.35 h60
  text "-" at 7218.8,6154.35 h60
  text "-" at 7840.35,6154.35 h60
  text "34" at 4891.17,6029.85 h60
  text "80.71mil (2.050mm)" at 5223.33,6029.85 h60
  text "PTH" at 5859.81,6029.85 h60
  text "Round" at 6119.01,6029.85 h60
  text "Top Layer - Bottom Layer" at 6494.25,6029.85 h60
  text "-" at 7218.8,6029.85 h60
  text "-" at 7840.35,6029.85 h60
  text "2" at 4891.17,5905.35 h60
  text "125.00mil (3.175mm)" at 5223.33,5905.35 h60
  text "PTH" at 5859.81,5905.35 h60
  text "Round" at 6119.01,5905.35 h60
  text "Top Layer - Bottom Layer" at 6494.25,5905.35 h60
  text "-" at 7218.8,5905.35 h60
  text "-" at 7840.35,5905.35 h60
  text "6" at 4891.17,5780.85 h60
  text "125.98mil (3.200mm)" at 5223.33,5780.85 h60
  text "PTH" at 5859.81,5780.85 h60
  text "Round" at 6119.01,5780.85 h60
  text "Top Layer - Bottom Layer" at 6494.25,5780.85 h60
  text "-" at 7218.8,5780.85 h60
  text "-" at 7840.35,5780.85 h60
  text "5" at 4891.17,5656.35 h60
  text "120.00mil (3.048mm)" at 5223.33,5656.35 h60
  text "NPTH" at 5859.81,5656.35 h60
  text "Slot" at 6119.01,5656.35 h60
  text "Top Layer - Bottom Layer" at 6494.25,5656.35 h60
  text "550.00mil (13.970mm)" at 7218.8,5656.35 h60
  text "430.00mil (10.922mm)" at 7840.35,5656.35 h60
  text "A" at 4565.2,5646.36 h55.33
  text "624 Total" at 4891.17,5531.85 h60
  text "Slot definitions :" at 4590.51,5444.7 h60
  text "Routed Path Length" at 5041.16,5444.7 h60
  text "= Calculated from tool start centre position to tool end centre position." at 5581.01,5444.7 h60
  text "Hole Length" at 5041.16,5394.9 h60
  text "= Routed Path Length + Tool Size = Slot length as defined in the PCB layout" at 5381.16,5394.9 h60
  text "FOR 7.87MIL DRILL +0/-7.87MIL" at 4523,5237 h60
  text "FOR 12MIL DRILL +0/-12MIL" at 4523,5133 h60
  text "FOR PTH DRILL +/-3MIL" at 4523,5024 h60
  text "FOR NPTH DRILL +/-2MIL" at 4528,4905 h60
  text ".Layer_Name" at 577,-858.49 h60
M17 Embedded Cavity:
  text ".Layer_Name" at 577,-858.49 h60
M18 Embedded Assembly:
  text ".Layer_Name" at 577,-858.49 h60
M19 Embedded Keepout:
  text ".Layer_Name" at 577,-858.49 h60

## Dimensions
0,0 to 0,4133.86 on M2 Board Dimensions
0,-400 to 1000,-400 on M2 Board Dimensions
0,0 to 9055.12,0 on M2 Board Dimensions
